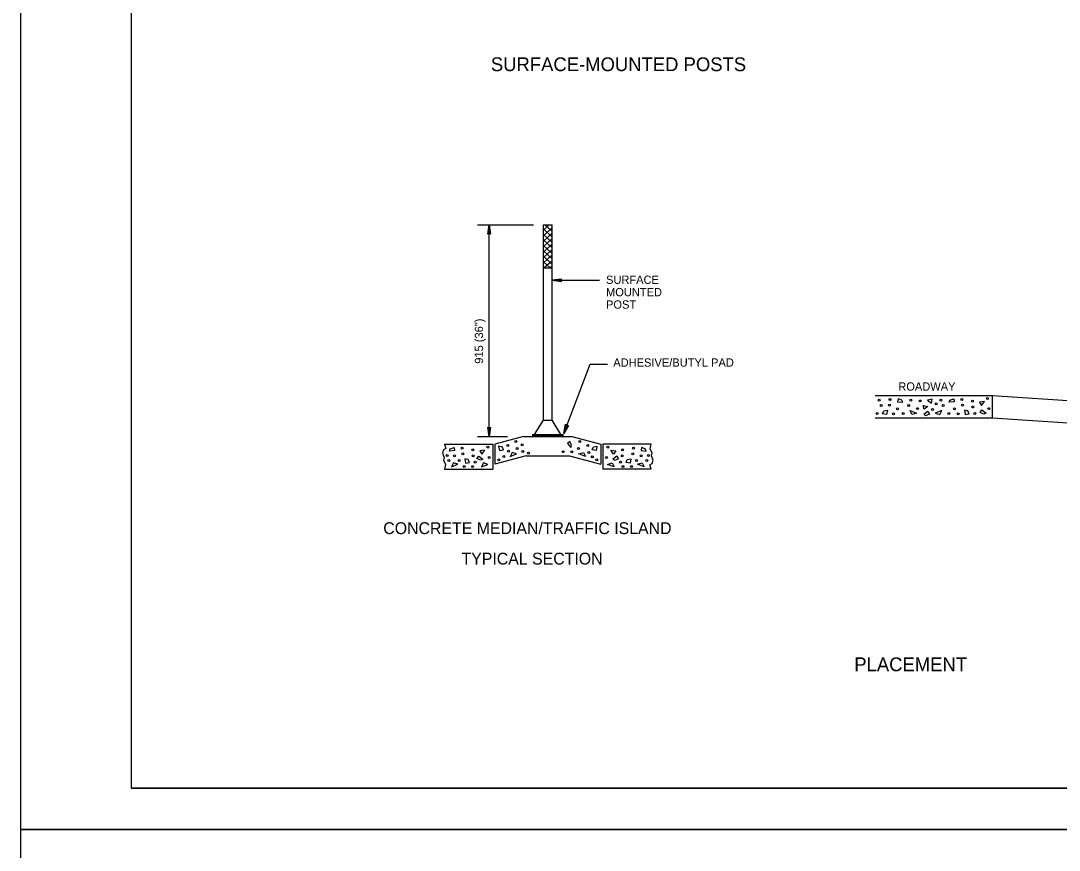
# Model space of a CAD drawing. Extents: x 640253 to 641999, y 298458 to 299646.
# Drawn here: x 640253.3 to 640629.6, y 299044.1 to 299344.9 of the extents above; entities that cross this region are included whole.
import ezdxf

# ---------------------------------------------------------------- set-up
doc = ezdxf.new("R2010")
doc.units = 0
for name, color, linetype in [('1', 7, 'Continuous'), ('2', 7, 'Continuous'), ('PLT-BNDY', 7, 'Continuous')]:
    doc.layers.add(name, color=color, linetype=linetype)

msp = doc.modelspace()

# ---------------------------------------------------------------- linework, layer by layer
at = {"layer": '1'}
for p, q in [((640293.31, 299630.63), (640293.31, 299066.63)), ((641079.31, 299066.63), (640293.31, 299066.63)), ((640293.31, 299066.63), (640879.31, 299066.63))]:
    msp.add_line(p, q, dxfattribs=at)
at = {"layer": '2'}
for p, q in [((640418.89, 299270.87), (640439.12, 299270.87)), ((640423.06, 299194.13), (640423.06, 299270.87)), ((640442.69, 299270.87), (640445.92, 299270.87)), ((640442.69, 299255.28), (640442.69, 299270.87)), ((640442.69, 299268.93), (640444.82, 299270.87)), ((640442.69, 299266.95), (640445.92, 299269.89)), ((640445.92, 299266.46), (640442.69, 299269.4)), ((640442.69, 299264.97), (640445.92, 299267.91)), ((640445.92, 299264.47), (640442.69, 299267.41)), ((640445.92, 299268.43), (640443.24, 299270.87)), ((640445.92, 299270.41), (640445.42, 299270.87)), ((640445.92, 299255.28), (640445.92, 299270.87)), ((640442.69, 299262.99), (640445.92, 299265.93)), ((640445.92, 299262.5), (640442.69, 299265.43)), ((640442.69, 299261.01), (640445.92, 299263.95)), ((640445.92, 299260.51), (640442.69, 299263.45)), ((640442.69, 299259.03), (640445.92, 299261.97)), ((640445.92, 299258.53), (640442.69, 299261.47)), ((640442.69, 299257.05), (640445.92, 299259.99)), ((640445.92, 299256.55), (640442.69, 299259.49)), ((640445.14, 299255.28), (640442.69, 299257.52)), ((640442.92, 299255.28), (640445.92, 299258.01)), ((640442.96, 299255.28), (640442.69, 299255.53)), ((640442.69, 299255.28), (640445.92, 299255.28)), ((640442.69, 299200.02), (640442.69, 299255.28)), ((640445.1, 299255.28), (640445.92, 299256.03)), ((640445.92, 299200.02), (640445.92, 299255.28)), ((640445.92, 299250.8), (640463, 299250.8)), ((640450.08, 299195.24), (640459.71, 299220.35)), ((640459.71, 299220.35), (640465.99, 299220.35)), ((640562.97, 299208.99), (640605.44, 299208.99)), ((640605.44, 299200.94), (640605.44, 299208.99)), ((640605.44, 299208.99), (640714.64, 299201.64)), ((640439.54, 299194.82), (640442.69, 299200.02)), ((640442.69, 299200.02), (640445.92, 299200.02)), ((640449.07, 299194.82), (640445.92, 299200.02)), ((640562.97, 299200.94), (640605.44, 299200.94)), ((640605.44, 299200.94), (640714.64, 299193.59)), ((640418.89, 299194.13), (640429.65, 299194.13)), ((640435.56, 299194.13), (640425.06, 299191.32)), ((640435.56, 299194.13), (640453.06, 299194.13)), ((640438.66, 299194.65), (640449.95, 299194.65)), ((640438.66, 299194.48), (640449.95, 299194.48)), ((640438.66, 299194.31), (640449.95, 299194.31)), ((640438.67, 299194.82), (640449.94, 299194.82)), ((640453.06, 299194.13), (640463.56, 299191.32)), ((640406.86, 299191.32), (640424.36, 299191.32)), ((640424.36, 299191.32), (640424.36, 299182.32)), ((640425.06, 299191.32), (640425.06, 299184.07)), ((640463.56, 299191.32), (640463.56, 299184.07)), ((640464.26, 299191.32), (640464.26, 299182.32)), ((640481.76, 299191.32), (640464.26, 299191.32)), ((640436.49, 299187.13), (640425.06, 299184.07)), ((640436.49, 299187.13), (640452.13, 299187.13)), ((640452.13, 299187.13), (640463.56, 299184.07)), ((640406.86, 299182.32), (640424.36, 299182.32)), ((640481.76, 299182.32), (640464.26, 299182.32))]:
    msp.add_line(p, q, dxfattribs=at)
for points in [[(640422.66, 299267.67), (640422.89, 299267.79), (640423.06, 299270.87), (640422.66, 299267.67), (640422.52, 299267.51), (640423.06, 299270.87), (640423.21, 299267.79), (640423.44, 299267.68), (640423.06, 299270.87), (640423.6, 299267.51), (640423.44, 299267.68)], [(640449.12, 299250.39), (640449, 299250.62), (640445.92, 299250.8), (640449.12, 299250.39), (640449.28, 299250.25), (640445.92, 299250.8), (640449, 299250.95), (640449.11, 299251.17), (640445.92, 299250.8), (640449.28, 299251.33), (640449.11, 299251.17)], [(640423.46, 299197.33), (640423.23, 299197.21), (640423.06, 299194.13), (640423.46, 299197.33), (640423.6, 299197.49), (640423.06, 299194.13), (640422.91, 299197.21), (640422.68, 299197.32), (640423.06, 299194.13), (640422.53, 299197.49), (640422.68, 299197.32)], [(640451.6, 299198.07), (640451.34, 299198.05), (640450.08, 299195.24), (640451.6, 299198.07), (640451.79, 299198.18), (640450.08, 299195.24), (640451.04, 299198.16), (640450.87, 299198.35), (640450.08, 299195.24), (640450.78, 299198.56), (640450.87, 299198.35)], [(640406.86, 299191.32), (640407.34, 299189.77), (640406.52, 299189.35), (640406.11, 299188.12), (640406.73, 299186.57), (640406.52, 299185.54), (640407.24, 299184), (640406.86, 299182.32)], [(640481.76, 299182.32), (640481.27, 299183.88), (640482.09, 299184.29), (640482.5, 299185.52), (640481.88, 299187.07), (640482.09, 299188.1), (640481.37, 299189.65), (640481.76, 299191.32)]]:
    msp.add_lwpolyline(points, dxfattribs=at)
for points in [[(640572.62, 299207.3), (640571.23, 299207.85), (640571.09, 299206.73), (640572.96, 299206.53)], [(640583.33, 299206.25), (640583.63, 299207.63), (640581.96, 299207.34)], [(640590.06, 299207.3), (640591.45, 299207.85), (640591.59, 299206.73), (640589.72, 299206.53)], [(640567.08, 299202.17), (640565.63, 299202.37), (640566.11, 299203.48), (640567.37, 299203.69)], [(640577.93, 299202.64), (640576.27, 299202.09), (640575.57, 299203.55)], [(640580.68, 299203.99), (640580.39, 299205.37), (640582.06, 299205.07)], [(640584.74, 299202.64), (640586.41, 299202.09), (640587.11, 299203.55)], [(640595.59, 299202.17), (640597.05, 299202.37), (640596.57, 299203.48), (640595.31, 299203.69)], [(640600.78, 299206.59), (640601.54, 299205.41), (640602.52, 299206.8)], [(640602.33, 299202.27), (640600.96, 299202.86), (640601.65, 299203.75), (640603.12, 299202.57)], [(640581.34, 299201.76), (640582.71, 299202.35), (640582.02, 299203.23), (640580.55, 299202.06)], [(640452.9, 299190.96), (640452.31, 299192.33), (640451.43, 299191.65), (640452.6, 299190.17)], [(640408.98, 299189.62), (640410.37, 299190.18), (640410.51, 299189.06), (640408.63, 299188.86)], [(640419.7, 299188.92), (640420.46, 299187.74), (640421.43, 299189.13)], [(640426.76, 299189.08), (640428.21, 299189.28), (640427.73, 299190.4), (640426.48, 299190.6)], [(640433.01, 299187.82), (640431.34, 299188.37), (640430.65, 299186.91)], [(640455.61, 299187.82), (640457.27, 299188.37), (640457.97, 299186.91)], [(640461.86, 299189.08), (640460.4, 299189.28), (640460.88, 299190.4), (640462.13, 299190.6)], [(640468.92, 299188.92), (640468.15, 299187.74), (640467.18, 299189.13)], [(640479.63, 299189.62), (640478.25, 299190.18), (640478.1, 299189.06), (640479.98, 299188.86)], [(640411.75, 299184.05), (640410.08, 299184.61), (640409.38, 299183.15)], [(640414.51, 299184.49), (640415.97, 299184.7), (640415.48, 299185.81), (640414.23, 299186.02)], [(640419.96, 299185.58), (640418.59, 299186.17), (640419.27, 299187.06), (640420.75, 299185.88)], [(640422.61, 299184), (640420.95, 299184.56), (640420.25, 299183.1)], [(640466, 299184), (640467.67, 299184.56), (640468.36, 299183.1)], [(640468.65, 299185.58), (640470.02, 299186.17), (640469.34, 299187.06), (640467.86, 299185.88)], [(640474.1, 299184.49), (640472.65, 299184.7), (640473.13, 299185.81), (640474.38, 299186.02)], [(640476.86, 299184.05), (640478.53, 299184.61), (640479.23, 299183.15)]]:
    msp.add_lwpolyline(points, close=True, dxfattribs=at)
for centre in [(640564.41, 299207.36), (640568.32, 299207.56), (640575.9, 299207.33), (640579.29, 299207.02), (640586.78, 299207.33), (640594.36, 299207.56), (640598.26, 299206.95), (640603.65, 299207.9), (640565.11, 299205.35), (640568.1, 299205.48), (640571, 299204.18), (640575.09, 299205.35), (640578.32, 299204.24), (640583.7, 299203.94), (640585.06, 299205.95), (640587.58, 299205.35), (640591.67, 299204.18), (640594.58, 299205.48), (640598.39, 299204.83), (640604.11, 299204.24), (640563.64, 299202.48), (640569.63, 299202.32), (640573.06, 299202.44), (640589.62, 299202.44), (640593.05, 299202.32), (640599.04, 299202.48), (640432.7, 299192.29), (640455.91, 299192.29), (640413.27, 299189.89), (640417.18, 299189.28), (640422.57, 299190.23), (640429.82, 299190.9), (640430.03, 299188.84), (640433.22, 299189.82), (640435.07, 299191.16), (640435.22, 299188.68), (640437.33, 299188.12), (640449.84, 299188.63), (640452.98, 299188.58), (640455.4, 299189.82), (640458.79, 299190.9), (640459.2, 299188.33), (640466.05, 299190.23), (640471.43, 299189.28), (640475.34, 299189.89), (640407.84, 299187.27), (640408.44, 299185.43), (640410.49, 299187.12), (640412.17, 299185.48), (640413.5, 299187.81), (640417.3, 299187.16), (640417.96, 299184.81), (640423.03, 299186.57), (640426.53, 299185.7), (640428.38, 299186.93), (640460.44, 299186.73), (640462.09, 299185.7), (640465.59, 299186.57), (640470.65, 299184.81), (640471.31, 299187.16), (640475.12, 299187.81), (640476.44, 299185.48), (640478.12, 299187.12), (640480.18, 299185.43), (640480.77, 299187.27), (640413.97, 299183.26), (640417.06, 299183.21), (640471.56, 299183.21), (640474.64, 299183.26)]:
    msp.add_circle(centre, 0.352, dxfattribs=at)
at = {"layer": 'PLT-BNDY'}
for points in [[(640253.31, 299645.63), (641094.31, 299645.63), (641094.31, 299051.63), (640253.31, 299051.63)], [(640253.31, 299051.63), (641094.31, 299051.63), (641094.31, 298457.63), (640253.31, 298457.63)]]:
    msp.add_lwpolyline(points, close=True, dxfattribs=at)

# ---------------------------------------------------------------- texts
at = {"layer": '2'}
for s, height, p in [('SURFACE-MOUNTED POSTS', 5, (640423.68, 299326.6)), ('SURFACE', 3, (640465.41, 299249.48)), ('MOUNTED', 3, (640465.41, 299244.98)), ('POST', 3, (640465.41, 299240.48)), ('ADHESIVE/BUTYL PAD', 3, (640468.03, 299219.46)), ('ROADWAY', 3, (640571.33, 299210.76)), ('CONCRETE MEDIAN/TRAFFIC ISLAND', 4.3, (640384.69, 299158.75)), ('TYPICAL SECTION', 4.3, (640413.04, 299147.71)), ('PLACEMENT', 5, (640555.38, 299109.04))]:
    msp.add_text(s, height=height, dxfattribs=at).set_placement(p)
msp.add_text('915 (36")', height=3, rotation=90, dxfattribs=at).set_placement((640420.86, 299220.52))

doc.saveas('drawing.dxf')
